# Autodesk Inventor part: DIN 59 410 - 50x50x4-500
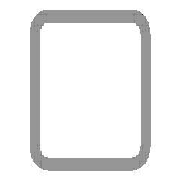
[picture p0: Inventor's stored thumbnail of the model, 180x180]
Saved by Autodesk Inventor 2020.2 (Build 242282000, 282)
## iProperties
Manager: www.cadconsulting.pl
Company: Fabian Stasiak CAD Consulting
Created: 2015-01
Part Number: DIN 59 410 - 50x50x4-500
Material: Stal, miękka
Description: Rurki stalowe o przekroju kwadratowym formowane na gorąco
Document SubType Name: Modellieren
Standard: DIN
Designer: F.Stasiak
Standards Organization: DIN
Language: pl-PL
Size Designation: 50x50x4
Categories: <MemberInstance><Categories><Category DisplayName="Kształtowniki konstrukcyjne" InternalName="089c4875-fa83-4c05-b084-43b9cc11f5ed" Mnemonic="GRDR"><CategoryPar
Stock Number: 50x50x4
Density: 7.85 g/cm^3
Appearance: Częściowo polerowana
Mass: 2781.62 g
Surface Area: 1785.63 cm^2
Volume: 354.346 cm^3
Catalog Web Link: www.expertbooks.pl
_CCFamilyMember: 40
_CCFamilyDisplayName: DIN 59410 (Kwadrat) - Rurki stalowe o przekroju kwadratowym formowane na gorąco
_FrameMemberDoc: Frame Member File
_Version: 15.0.0
_GetPNFromCC: 1
G_W: 50,000 mm
G_H: 50,000 mm
G_L: 500,000 mm
+2D715D7D-54E3-4B96-B3EA-78B1ABAF3CCE+CUTDETAIL4: Wytnij
+52161554-C0FF-430F-9C38-4285BB8A8ADB+CUTDETAIL5: Wytnij
IsCustomPart: 1
Author: F.Stasiak
Subject: Zbiór ćwiczeń. Autodesk Inventor 2020. Kurs Professional
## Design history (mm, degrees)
node "Płaszczyzna początkowa"
node "Płaszczyzna końcowa"
sketch "Szkic"
  geometry: L1 (-17, 25)-(17, 25); L2 (25, 17)-(25, -17); L3 (17, -25)-(-17, -25); L4 (-25, -17)-(-25, 17); L5 (-37.32, 0)-(37.32, 0) reference; L6 (0, -37.32)-(0, 37.32) reference; L7 (-17, 21)-(17, 21); L8 (21, 17)-(21, -17); L9 (17, -21)-(-17, -21); L10 (-21, -17)-(-21, 17); A1 r 8 centre (-17, 17) between (-17, 25) and (-25, 17); A2 r 8 centre (17, 17) between (25, 17) and (17, 25); A3 r 8 centre (17, -17) between (17, -25) and (25, -17); A4 r 8 centre (-17, -17) between (-25, -17) and (-17, -25); A5 r 4 centre (-17, 17) between (-17, 21) and (-21, 17); A6 r 4 centre (17, 17) between (21, 17) and (17, 21); A7 r 4 centre (17, -17) between (17, -21) and (21, -17); A8 r 4 centre (-17, -17) between (-21, -17) and (-17, -21); 3 further points
  constraints: 16 end point, 16 point on circle, 8 centre point, 8 tangent, 6 point on line, 4 parallel, 3 equal radius, 3 perpendicular, 1 horizontal, 7 other
  dimensions: "b" = 50 distance of point (-25, 25) point (25, 25); "msp_r" = 8 radius of A1 (= 2 x ParT); "d8" = 25 distance between parallel lines of L4 L6 (= d9); "d9" = 25 distance between parallel lines of L3 L5 (= 0.5 x b); "d10" = 4 distance between parallel lines of L3 L9 (= ParT)
extrude "Bryła" new body sketch "Szkic" taper "d4" = 0 deg; stored distance "NLG" = 10
node "Driven Length"
  sketch "Sketch2"
    geometry: L1 (0, 0)-(10, 0) reference
    constraints: 2 end point, 1 horizontal
  workplane "Work Plane3"
  sketch "Sketch3"
    geometry: L1 (-2, 25)-(12, 25) reference; L2 (-2, 525)-(12, 525) reference
    dimensions: "d14" = 500 distance between parallel lines of L1 L2 (derived)
node "Płaszczyzna konstrukcyjna7"
feature "Podział4"
node "Płaszczyzna konstrukcyjna8"
feature "Podział5"
body "Solid1"
other parameters: "ParT" = 4, "G_OFFSET_START" = -25 [user parameter; used in 1 equation term], "G_OFFSET_END" = 25 [user parameter; used in 1 equation term], "d11" = 25 (= -G_OFFSET_START), "d12" = 525 (= G_OFFSET_END + B_L), "G_L" = 500 (= d14) [user parameter], "d13" = 90 deg
